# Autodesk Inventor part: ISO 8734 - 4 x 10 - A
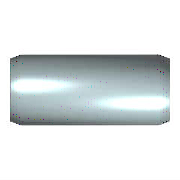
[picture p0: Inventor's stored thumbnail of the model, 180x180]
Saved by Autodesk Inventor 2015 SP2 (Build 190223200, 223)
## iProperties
IsCustomPart: 0
Created: 2012-02
Part Number: ISO 8734 - 4 x 10 - A
Material: Stahl
Description: Zylinderstift
Document SubType Name: Modeling
Standard: ISO 8734
Designer: rYan
Standards Organization: DIN
Language: de-DE
Size Designation: 4 x 10 - A
Categories: <MemberInstance><Categories><Category DisplayName="Verbindungselemente" InternalName="e4da775c-781d-43d5-af7c-5136215cf5a6" Mnemonic="FSTN"><Category DisplayNam
Density: 7.85 g/cm^3
Mass: 0.976264 g
Surface Area: 1.466 cm^2
Volume: 0.124365 cm^3
Appearance: Platte
Author: rYan
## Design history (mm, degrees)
sketch "Skizze"
  geometry: C1 r 2 at (0, 0); 1 further point
  constraints: 1 centre point, 1 coincident
  dimensions: "d1" = 4 diameter of C1 (= NND)
extrude "Körper" new body sketch "Skizze" distance "d2" = 10 (= NLG); taper "d3" = 0 deg
body "Solid1"
chamfer "Fase1" distance "d4" = 0.63 (= PHH); stored, may be unused: angle "d5" = 15 deg (= FAWI), second distance "d11" = 0.63 (= PHH)
chamfer "Fase2" distance "d8" = 0.63 (= PHH); stored, may be unused: angle "d9" = 15 deg (= FAWI), second distance "d12" = 0.63 (= PHH)
other parameters: "NND" = 4 [user parameter; used in 1 equation term], "NLG" = 10 [user parameter; used in 1 equation term], "PHH" = 0.63 [user parameter; used in 5 equation terms], "FAWI" = 15 deg [user parameter; used in 2 equation terms], "d13" = 0, "d15" = 0, "d16" = 0, "PHH2" = 0.63 (= PHH) [user parameter], "FAWI2" = 15 deg [user parameter]
